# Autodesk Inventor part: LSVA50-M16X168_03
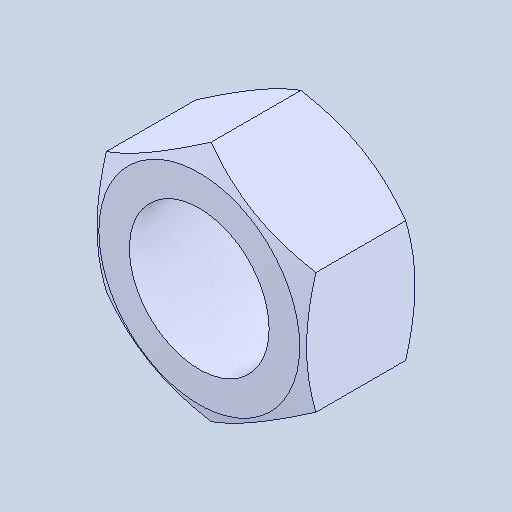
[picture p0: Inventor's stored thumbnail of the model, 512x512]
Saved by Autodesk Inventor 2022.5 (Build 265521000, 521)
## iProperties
Created: 2024-08
Part Number: LSVA50-M16X168_03
Material: 一般
Document SubType Name: Modeling
Designer: ImaoCorp
Density: 1 g/cm^3
Appearance: 既定
Author: ImaoCorp
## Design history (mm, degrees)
feature "LSVA50-M16X168_03"
node "ソリッド1"
